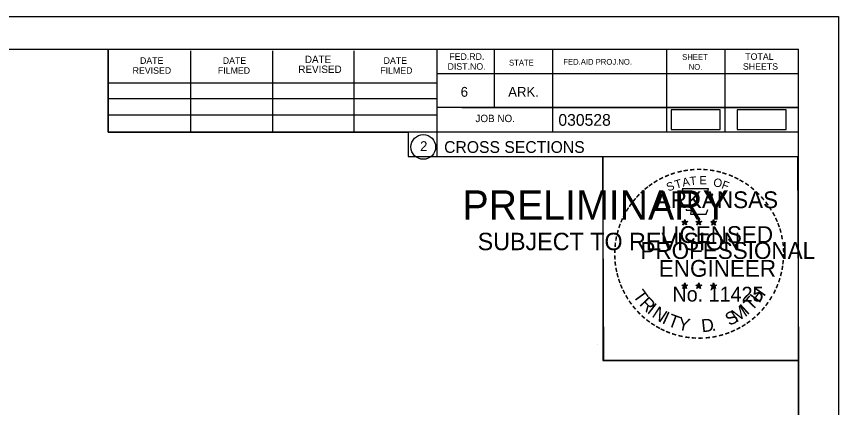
# Model space of a CAD drawing. Extents: x 1370843 to 1371177, y 380307 to 382654.
# Drawn here: x 1371078.7 to 1371176.6, y 382394.2 to 382440.8 of the extents above; entities that cross this region are included whole.
import ezdxf

# ---------------------------------------------------------------- set-up
doc = ezdxf.new("R2010")
doc.units = 0
for name, color, linetype in [('R_Border', 7, 'Continuous'), ('R_Border PE', 7, 'Continuous'), ('R_Border Prem', 7, 'Continuous'), ('R_Draft', 7, 'Continuous'), ('R_No Plot', 7, 'Continuous')]:
    doc.layers.add(name, color=color, linetype=linetype)

msp = doc.modelspace()

# ---------------------------------------------------------------- linework, layer by layer
at = {"layer": 'R_Border'}
for p, q in [((1370855.709, 382436.95), (1371171.889, 382436.95)), ((1371089.629, 382427.07), (1371089.629, 382436.95)), ((1371099.489, 382427.07), (1371099.489, 382436.75)), ((1371109.249, 382427.07), (1371109.249, 382436.75)), ((1371118.929, 382427.07), (1371118.929, 382436.75)), ((1371128.789, 382436.95), (1371128.789, 382424.15)), ((1371135.629, 382436.95), (1371135.629, 382430.01)), ((1371142.569, 382436.95), (1371142.569, 382427.07)), ((1371156.149, 382436.95), (1371156.149, 382427.07)), ((1371163.089, 382436.95), (1371163.089, 382427.07)), ((1371171.889, 382231.49), (1371171.889, 382436.95)), ((1371171.889, 382434.01), (1371128.789, 382434.01)), ((1371171.889, 382434.03), (1371171.889, 382434.03)), ((1371089.629, 382432.93), (1371128.789, 382432.93)), ((1371089.629, 382431.07), (1371128.789, 382431.07)), ((1371171.889, 382430.01), (1371128.789, 382430.01)), ((1371131.749, 382430.01), (1371171.889, 382430.01)), ((1371089.629, 382427.07), (1371089.629, 382429.13)), ((1371089.629, 382429.13), (1371128.789, 382429.13)), ((1371171.889, 382427.07), (1371089.629, 382427.07)), ((1371128.789, 382424.15), (1371171.889, 382424.15))]:
    msp.add_line(p, q, dxfattribs=at)
msp.add_circle((1371127.176, 382425.286), 1.467, dxfattribs=at)
at = {"layer": 'R_Border PE'}
for p, q in [((1371157.974, 382416.405), (1371158.323, 382416.294)), ((1371157.974, 382416.405), (1371158.227, 382416.36)), ((1371157.974, 382416.405), (1371158.211, 382416.283)), ((1371158.107, 382415.997), (1371158.323, 382416.294)), ((1371158.107, 382415.997), (1371158.233, 382416.241)), ((1371158.107, 382415.997), (1371158.321, 382416.214)), ((1371158.323, 382416.659), (1371158.282, 382416.407)), ((1371158.536, 382415.997), (1371158.321, 382416.211)), ((1371158.323, 382416.294), (1371158.323, 382416.659)), ((1371158.323, 382416.659), (1371158.372, 382416.409)), ((1371158.67, 382416.405), (1371158.323, 382416.294)), ((1371158.536, 382415.997), (1371158.323, 382416.294)), ((1371158.67, 382416.405), (1371158.384, 382416.356)), ((1371158.536, 382415.997), (1371158.399, 382416.288)), ((1371158.67, 382416.405), (1371158.466, 382416.303)), ((1371159.644, 382416.405), (1371159.993, 382416.294)), ((1371159.644, 382416.405), (1371159.897, 382416.36)), ((1371159.644, 382416.405), (1371159.881, 382416.283)), ((1371159.777, 382415.997), (1371159.993, 382416.294)), ((1371159.777, 382415.997), (1371159.903, 382416.241)), ((1371159.777, 382415.997), (1371159.991, 382416.214)), ((1371159.993, 382416.659), (1371159.952, 382416.407)), ((1371160.206, 382415.997), (1371159.991, 382416.211)), ((1371159.993, 382416.294), (1371159.993, 382416.659)), ((1371159.993, 382416.659), (1371160.042, 382416.409)), ((1371160.34, 382416.405), (1371159.993, 382416.294)), ((1371160.206, 382415.997), (1371159.993, 382416.294)), ((1371160.34, 382416.405), (1371160.054, 382416.356)), ((1371160.206, 382415.997), (1371160.069, 382416.288)), ((1371160.34, 382416.405), (1371160.136, 382416.303)), ((1371161.408, 382416.393), (1371161.757, 382416.282)), ((1371161.408, 382416.393), (1371161.661, 382416.348)), ((1371161.408, 382416.393), (1371161.645, 382416.271)), ((1371161.541, 382415.985), (1371161.757, 382416.282)), ((1371161.541, 382415.985), (1371161.667, 382416.229)), ((1371161.541, 382415.985), (1371161.755, 382416.202)), ((1371161.757, 382416.647), (1371161.716, 382416.395)), ((1371161.97, 382415.985), (1371161.755, 382416.199)), ((1371161.757, 382416.282), (1371161.757, 382416.647)), ((1371161.757, 382416.647), (1371161.806, 382416.397)), ((1371162.104, 382416.393), (1371161.757, 382416.282)), ((1371161.97, 382415.985), (1371161.757, 382416.282)), ((1371162.104, 382416.393), (1371161.818, 382416.344)), ((1371161.97, 382415.985), (1371161.833, 382416.276)), ((1371162.104, 382416.393), (1371161.9, 382416.291)), ((1371158.319, 382409.086), (1371158.278, 382408.834)), ((1371158.319, 382408.721), (1371158.319, 382409.086)), ((1371158.319, 382409.086), (1371158.368, 382408.836)), ((1371159.988, 382409.086), (1371159.947, 382408.834)), ((1371159.988, 382408.721), (1371159.988, 382409.086)), ((1371159.988, 382409.086), (1371160.037, 382408.836)), ((1371161.755, 382409.076), (1371161.714, 382408.824)), ((1371161.755, 382408.711), (1371161.755, 382409.076)), ((1371161.755, 382409.076), (1371161.804, 382408.826)), ((1371157.97, 382408.832), (1371158.319, 382408.721)), ((1371157.97, 382408.832), (1371158.223, 382408.787)), ((1371157.97, 382408.832), (1371158.207, 382408.71)), ((1371158.103, 382408.424), (1371158.319, 382408.721)), ((1371158.103, 382408.424), (1371158.229, 382408.668)), ((1371158.103, 382408.424), (1371158.317, 382408.641)), ((1371158.532, 382408.424), (1371158.317, 382408.638)), ((1371158.666, 382408.832), (1371158.319, 382408.721)), ((1371158.532, 382408.424), (1371158.319, 382408.721)), ((1371158.666, 382408.832), (1371158.38, 382408.783)), ((1371158.532, 382408.424), (1371158.395, 382408.715)), ((1371158.666, 382408.832), (1371158.462, 382408.73)), ((1371159.639, 382408.832), (1371159.988, 382408.721)), ((1371159.639, 382408.832), (1371159.892, 382408.787)), ((1371159.639, 382408.832), (1371159.876, 382408.71)), ((1371159.772, 382408.424), (1371159.988, 382408.721)), ((1371159.772, 382408.424), (1371159.898, 382408.668)), ((1371159.772, 382408.424), (1371159.986, 382408.641)), ((1371160.201, 382408.424), (1371159.986, 382408.638)), ((1371160.335, 382408.832), (1371159.988, 382408.721)), ((1371160.201, 382408.424), (1371159.988, 382408.721)), ((1371160.335, 382408.832), (1371160.049, 382408.783)), ((1371160.201, 382408.424), (1371160.064, 382408.715)), ((1371160.335, 382408.832), (1371160.131, 382408.73)), ((1371161.406, 382408.822), (1371161.755, 382408.711)), ((1371161.406, 382408.822), (1371161.659, 382408.777)), ((1371161.406, 382408.822), (1371161.643, 382408.7)), ((1371161.539, 382408.414), (1371161.755, 382408.711)), ((1371161.539, 382408.414), (1371161.665, 382408.658)), ((1371161.539, 382408.414), (1371161.753, 382408.631)), ((1371161.968, 382408.414), (1371161.753, 382408.628)), ((1371162.102, 382408.822), (1371161.755, 382408.711)), ((1371161.968, 382408.414), (1371161.755, 382408.711)), ((1371162.102, 382408.822), (1371161.816, 382408.773)), ((1371161.968, 382408.414), (1371161.831, 382408.705)), ((1371162.102, 382408.822), (1371161.898, 382408.72))]:
    msp.add_line(p, q, dxfattribs=at)
for points in [[(1371158.015, 382420.283), (1371158.284, 382419.456)], [(1371161.526, 382419.361), (1371161.668, 382419.645), (1371160.983, 382419.621), (1371161.131, 382420.283), (1371158.015, 382420.283)], [(1371158.507, 382417.86), (1371158.507, 382417.773), (1371159.07, 382417.754), (1371159.016, 382417.281), (1371160.886, 382417.281), (1371161.087, 382417.817)], [(1371158.323, 382416.659), (1371158.536, 382415.997), (1371157.974, 382416.405), (1371158.67, 382416.405), (1371158.107, 382415.997), (1371158.323, 382416.659)], [(1371159.993, 382416.659), (1371160.206, 382415.997), (1371159.644, 382416.405), (1371160.34, 382416.405), (1371159.777, 382415.997), (1371159.993, 382416.659)], [(1371161.757, 382416.647), (1371161.97, 382415.985), (1371161.408, 382416.393), (1371162.104, 382416.393), (1371161.541, 382415.985), (1371161.757, 382416.647)], [(1371158.319, 382409.086), (1371158.532, 382408.424), (1371157.97, 382408.832), (1371158.666, 382408.832), (1371158.103, 382408.424), (1371158.319, 382409.086)], [(1371159.988, 382409.086), (1371160.201, 382408.424), (1371159.639, 382408.832), (1371160.335, 382408.832), (1371159.772, 382408.424), (1371159.988, 382409.086)], [(1371161.755, 382409.076), (1371161.968, 382408.414), (1371161.406, 382408.822), (1371162.102, 382408.822), (1371161.539, 382408.414), (1371161.755, 382409.076)]]:
    msp.add_lwpolyline(points, dxfattribs=at)
for centre, radius in [((1371158.322, 382416.293), 0.172), ((1371158.322, 382416.293), 0.145), ((1371158.322, 382416.293), 0.116), ((1371158.322, 382416.293), 0.0991), ((1371158.322, 382416.293), 0.0747), ((1371158.322, 382416.293), 0.0495), ((1371158.322, 382416.293), 0.0296), ((1371159.992, 382416.293), 0.172), ((1371159.992, 382416.293), 0.145), ((1371159.992, 382416.293), 0.116), ((1371159.992, 382416.293), 0.0991), ((1371159.992, 382416.293), 0.0747), ((1371159.992, 382416.293), 0.0495), ((1371159.992, 382416.293), 0.0296), ((1371161.756, 382416.281), 0.172), ((1371161.756, 382416.281), 0.145), ((1371161.756, 382416.281), 0.116), ((1371161.756, 382416.281), 0.0991), ((1371161.756, 382416.281), 0.0747), ((1371161.756, 382416.281), 0.0495), ((1371161.756, 382416.281), 0.0296), ((1371158.318, 382408.72), 0.172), ((1371158.318, 382408.72), 0.145), ((1371159.987, 382408.72), 0.172), ((1371159.987, 382408.72), 0.145), ((1371161.754, 382408.71), 0.172), ((1371161.754, 382408.71), 0.145), ((1371158.318, 382408.72), 0.116), ((1371158.318, 382408.72), 0.0991), ((1371158.318, 382408.72), 0.0747), ((1371158.318, 382408.72), 0.0495), ((1371158.318, 382408.72), 0.0296), ((1371159.987, 382408.72), 0.116), ((1371159.987, 382408.72), 0.0991), ((1371159.987, 382408.72), 0.0747), ((1371159.987, 382408.72), 0.0495), ((1371159.987, 382408.72), 0.0296), ((1371161.754, 382408.71), 0.116), ((1371161.754, 382408.71), 0.0991), ((1371161.754, 382408.71), 0.0747), ((1371161.754, 382408.71), 0.0495), ((1371161.754, 382408.71), 0.0296)]:
    msp.add_circle(centre, radius, dxfattribs=at)
at = {"layer": 'R_Draft'}
for points in [[(1371156.702, 382427.385), (1371162.536, 382427.385), (1371162.536, 382429.695), (1371156.702, 382429.695)], [(1371164.572, 382427.385), (1371170.406, 382427.385), (1371170.406, 382429.695), (1371164.572, 382429.695)]]:
    msp.add_lwpolyline(points, close=True, dxfattribs=at)
at = {"layer": 'R_No Plot'}
for p, q in [((1370843.308, 382440.845), (1371176.642, 382440.845)), ((1371147.923, 382401.695), (1371147.923, 382401.695))]:
    msp.add_line(p, q, dxfattribs=at)
for points in [[(1370843.302, 382440.845), (1371176.642, 382440.845), (1371176.642, 382227.507), (1370843.302, 382227.507)], [(1371089.629, 382436.95), (1371089.629, 382427.07), (1371125.361, 382427.07), (1371125.361, 382424.15), (1371148.561, 382424.15), (1371148.561, 382399.818), (1371171.889, 382399.818), (1371171.889, 382231.49), (1370855.709, 382231.49), (1370855.709, 382436.95)], [(1371148.561, 382424.15), (1371171.768, 382424.15), (1371171.889, 382399.818), (1371148.681, 382399.818)]]:
    msp.add_lwpolyline(points, close=True, dxfattribs=at)

# ---------------------------------------------------------------- texts
at = {"layer": 'R_Border'}
for s, height, p in [('FED.RD.', 0.7819, (1371130.269, 382435.67)), ('SHEET', 0.684, (1371158.009, 382435.67)), ('TOTAL', 0.7819, (1371165.529, 382435.67)), ('DATE', 0.7819, (1371093.429, 382435.19)), ('DATE', 0.7819, (1371103.289, 382435.19)), ('DATE', 0.8792, (1371113.069, 382435.29)), ('DATE', 0.7819, (1371122.449, 382435.19)), ('DIST.NO.', 0.7819, (1371130.069, 382434.49)), ('STATE', 0.684, (1371137.389, 382434.99)), ('FED.AID PROJ.NO.', 0.684, (1371143.849, 382435.09)), ('SHEETS', 0.7819, (1371165.249, 382434.49)), ('REVISED', 0.7819, (1371092.549, 382434.01)), ('FILMED', 0.7819, (1371102.709, 382434.01)), ('REVISED', 0.8792, (1371112.289, 382434.11)), ('FILMED', 0.7819, (1371122.049, 382434.01)), ('NO.', 0.684, (1371158.789, 382434.49)), ('6', 1.172, (1371131.629, 382431.27)), ('ARK.', 1.1723, (1371137.289, 382431.27)), ('JOB NO.', 0.8792, (1371133.389, 382428.25)), ('030528', 1.4, (1371143.265, 382427.81)), ('2', 1.172, (1371126.793, 382424.799)), ('CROSS SECTIONS', 1.4, (1371129.653, 382424.58))]:
    msp.add_text(s, height=height, rotation=360, dxfattribs=at).set_placement(p)
at = {"layer": 'R_Border PE'}
for s, height, rotation, p in [('-', 1.6, 10.21935, (1371158.191, 382421.813)), ('-', 1.6, 5.89682, (1371158.92, 382421.923)), ('-', 1.6, 0.18623, (1371159.692, 382421.995)), ('-', 1.6, 357.74304, (1371160.415, 382421.982)), ('-', 1.6, 352.16172, (1371161.159, 382421.926)), ('-', 1.6, 28.79182, (1371155.496, 382420.824)), ('-', 1.6, 24.30721, (1371156.129, 382421.141)), ('-', 1.6, 19.17608, (1371156.763, 382421.41)), ('-', 1.6, 13.63015, (1371157.513, 382421.651)), ('A', 1, 11.21318, (1371158.11, 382420.543)), ('T', 1, 6.02276, (1371158.959, 382420.709)), ('E', 1, 0.83234, (1371160.064, 382420.819)), ('-', 1.6, 347.20489, (1371161.878, 382421.812)), ('-', 1.6, 342.3362, (1371162.513, 382421.657)), ('-', 1.6, 337.85509, (1371163.248, 382421.434)), ('-', 1.6, 334.12109, (1371163.879, 382421.163)), ('-', 1.6, 38.95066, (1371153.845, 382419.681)), ('-', 1.6, 36.23174, (1371154.321, 382420.059)), ('-', 1.6, 34.06357, (1371154.899, 382420.454)), ('S', 1, 21.59401, (1371156.37, 382419.961)), ('T', 1, 16.4036, (1371157.284, 382420.292)), ('O', 1, 350.4515, (1371161.668, 382420.609)), ('F', 1, 340.07066, (1371162.622, 382420.381)), ('-', 1.6, 329.64089, (1371164.458, 382420.88)), ('-', 1.6, 325.86266, (1371165.101, 382420.519)), ('-', 1.6, 48.42305, (1371152.964, 382418.786)), ('-', 1.6, 42.96224, (1371153.412, 382419.264)), ('ARKANSAS', 2, 360, (1371154.868, 382417.995)), ('-', 1.6, 320.52971, (1371165.711, 382420.093)), ('-', 1.6, 315.57859, (1371166.31, 382419.605)), ('-', 1.6, 54.23247, (1371152.148, 382417.733)), ('-', 1.6, 50.61417, (1371152.561, 382418.3)), ('-', 1.6, 309.87973, (1371166.879, 382419.055)), ('-', 1.6, 306.65218, (1371167.404, 382418.453)), ('-', 1.6, 58.07063, (1371151.823, 382417.206)), ('-', 1.4, 303.67529, (1371167.89, 382417.885)), ('-', 1.6, 67.77427, (1371151.251, 382415.981)), ('-', 1.6, 62.87135, (1371151.51, 382416.592)), ('-', 1.6, 299.66835, (1371168.209, 382417.278)), ('-', 1.6, 294.66279, (1371168.533, 382416.666)), ('-', 1.6, 72.39447, (1371151.032, 382415.351)), ('LICENSED', 2, 360, (1371155.465, 382413.846)), ('DWB', 0.01, 360, (1371158.31, 382416.289)), ('DWB', 0.01, 360, (1371159.98, 382416.289)), ('DWB', 0.01, 360, (1371161.744, 382416.278)), ('-', 1.6, 290.57283, (1371168.79, 382416.089)), ('-', 1.6, 75.46096, (1371150.835, 382414.637)), ('-', 1.6, 285.12326, (1371169.024, 382415.509)), ('-', 1.6, 280.54934, (1371169.224, 382414.767)), ('-', 1.6, 85.18634, (1371150.627, 382413.233)), ('-', 1.6, 81.20126, (1371150.703, 382413.924)), ('PROFESSIONAL', 2, 360, (1371153.042, 382411.942)), ('-', 1.6, 276.59616, (1371169.386, 382413.999)), ('-', 1.6, 89.06224, (1371150.602, 382412.532)), ('-', 1.6, 274.33011, (1371169.446, 382413.277)), ('-', 1.6, 94.19588, (1371150.637, 382411.807)), ('ENGINEER', 2, 360, (1371155.229, 382409.817)), ('-', 1.6, 263.5172, (1371169.461, 382411.979)), ('-', 1.6, 269.94067, (1371169.48, 382412.645)), ('-', 1.6, 98.94793, (1371150.709, 382411.14)), ('-', 1.6, 101.71495, (1371150.844, 382410.407)), ('-', 1.6, 260.99529, (1371169.39, 382411.325)), ('-', 1.6, 105.45785, (1371151.006, 382409.812)), ('-', 1.6, 255.7626, (1371169.28, 382410.647)), ('-', 1.6, 109.08742, (1371151.221, 382409.181)), ('-', 1.6, 114.06432, (1371151.475, 382408.585)), ('-', 1.6, 247.88866, (1371168.876, 382409.254)), ('-', 1.6, 252.86809, (1371169.099, 382409.927)), ('-', 1.6, 115.72885, (1371151.78, 382407.967)), ('T', 1.54, 306.04056, (1371152.078, 382407.559)), ('No. 11425', 1.757, 360, (1371156.856, 382406.866)), ('DWB', 0.01, 360, (1371158.306, 382408.716)), ('DWB', 0.01, 360, (1371159.975, 382408.716)), ('DWB', 0.01, 360, (1371161.742, 382408.706)), ('H', 1.54, 54.60883, (1371167.199, 382406.595)), ('-', 1.6, 244.61971, (1371168.614, 382408.625)), ('-', 1.6, 120.44712, (1371152.137, 382407.381)), ('-', 1.6, 125.89344, (1371152.54, 382406.82)), ('R', 1.54, 314.00497, (1371152.841, 382406.512)), ('T', 1.54, 46.64442, (1371166.309, 382405.652)), ('-', 1.6, 239.07125, (1371168.22, 382407.873)), ('-', 1.6, 130.71812, (1371153.002, 382406.268)), ('I', 1.54, 321.96938, (1371153.741, 382405.58)), ('N', 1.54, 326.50021, (1371154.309, 382405.108)), ('M', 1.54, 32.65632, (1371164.463, 382404.327)), ('I', 1.54, 42.11359, (1371165.747, 382405.174)), ('-', 1.6, 231.25377, (1371167.388, 382406.654)), ('-', 1.6, 233.84524, (1371167.818, 382407.22)), ('-', 1.6, 134.22381, (1371153.519, 382405.723)), ('-', 1.6, 138.93382, (1371154.044, 382405.259)), ('I', 1.54, 335.36034, (1371155.517, 382404.322)), ('T', 1.54, 339.89117, (1371156.178, 382403.995)), ('Y', 1.54, 347.85558, (1371157.395, 382403.549)), ('S', 1.54, 26.9312, (1371163.624, 382403.921)), ('-', 1.6, 221.08509, (1371166.387, 382405.581)), ('-', 1.6, 225.76533, (1371166.909, 382406.09)), ('-', 1.6, 144.64634, (1371154.6, 382404.853)), ('-', 1.6, 148.08978, (1371155.161, 382404.482)), ('-', 1.6, 151.57039, (1371155.74, 382404.157)), ('D', 1.54, 6.39691, (1371160.38, 382403.191)), ('-', 1.6, 212.24909, (1371165.304, 382404.722)), ('-', 1.6, 215.73633, (1371165.838, 382405.109)), ('-', 1.6, 154.60019, (1371156.262, 382403.91)), ('-', 1.6, 158.56121, (1371156.886, 382403.656)), ('-', 1.6, 162.79826, (1371157.573, 382403.443)), ('.', 1.54, 13.76417, (1371161.572, 382403.318)), ('-', 1.6, 195.47429, (1371162.826, 382403.542)), ('-', 1.6, 200.71842, (1371163.503, 382403.784)), ('-', 1.6, 204.25161, (1371164.122, 382404.057)), ('-', 1.6, 207.35684, (1371164.746, 382404.376)), ('-', 1.6, 167.55551, (1371158.288, 382403.279)), ('-', 1.6, 173.11546, (1371159.06, 382403.169)), ('-', 1.6, 176.51827, (1371159.808, 382403.116)), ('-', 1.6, 181.59176, (1371160.552, 382403.135)), ('-', 1.6, 185.81666, (1371161.361, 382403.211)), ('-', 1.6, 191.28576, (1371162.097, 382403.343))]:
    msp.add_text(s, height=height, rotation=rotation, dxfattribs=at).set_placement(p)
at = {"layer": 'R_Border Prem'}
for s, height, p in [('PRELIMINARY', 3.5, (1371131.84, 382416.613)), ('DWB', 0.01, (1371132.587, 382418.462)), ('SUBJECT TO REVISION', 2.07511, (1371133.649, 382412.984))]:
    msp.add_text(s, height=height, rotation=360, dxfattribs=at).set_placement(p)

doc.saveas('drawing.dxf')
